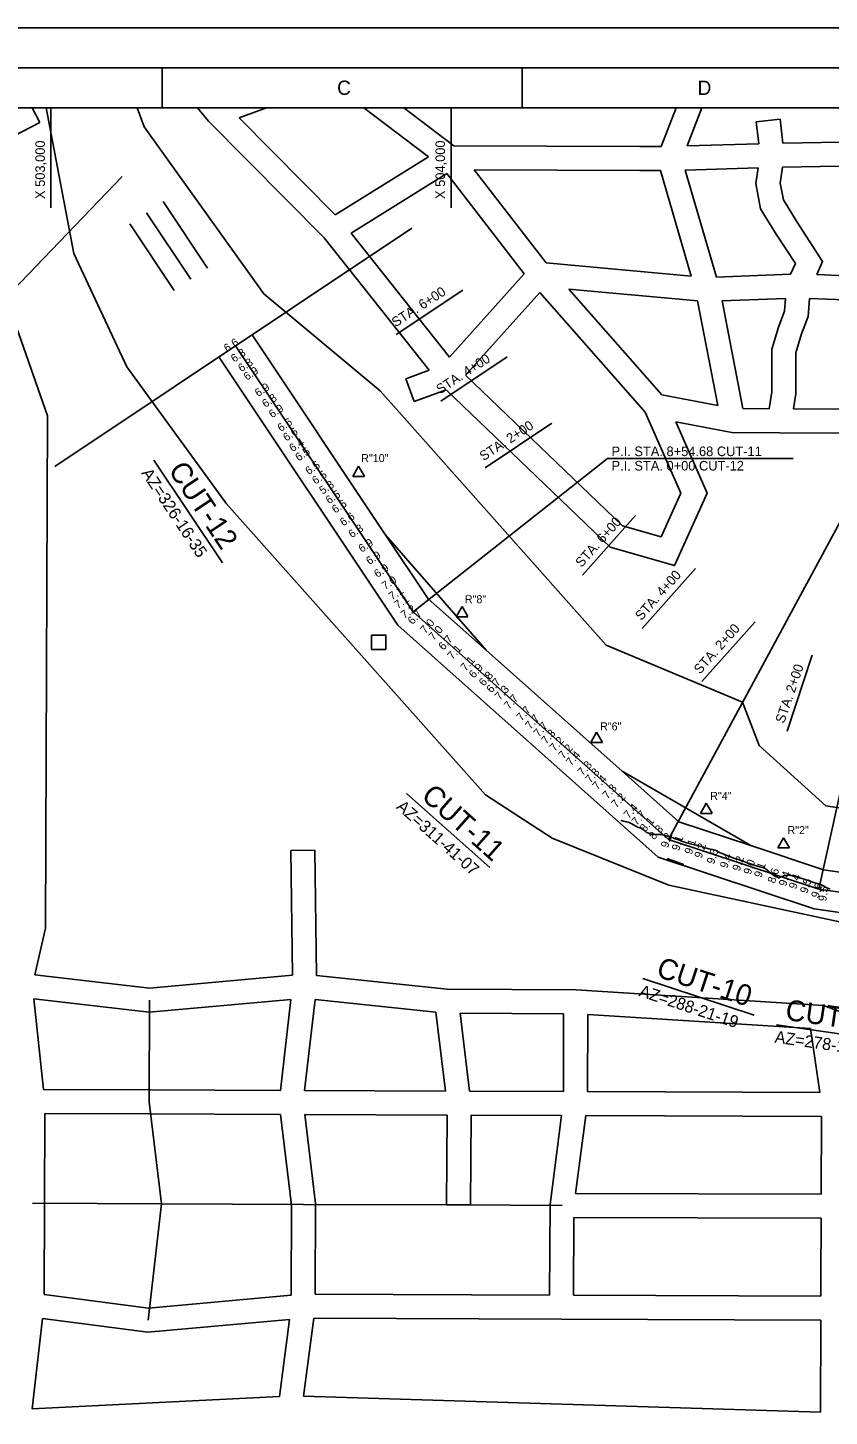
# Model space of a CAD drawing. Extents: x 501128 to 509328, y 1314906 to 1320706.
# Drawn here: x 502942 to 504945, y 1317236 to 1320706 of the extents above; entities that cross this region are included whole.
import ezdxf

# ---------------------------------------------------------------- set-up
doc = ezdxf.new("R2010")
doc.units = 0
for name, color, linetype in [('G-ANNO-TTLB', 7, 'Continuous'), ('Level 1', 7, 'Continuous'), ('Level 2', 7, 'Continuous'), ('Level 3', 7, 'Continuous'), ('Level 32', 7, 'Continuous'), ('Level 49', 7, 'Continuous'), ('Level 5', 7, 'Continuous'), ('Level 50', 7, 'Continuous'), ('Level 51', 7, 'Continuous'), ('Level 52', 7, 'Continuous'), ('Level 55', 7, 'Continuous'), ('Level 56', 7, 'Continuous'), ('Level 58', 7, 'Continuous'), ('Level 6', 7, 'Continuous')]:
    doc.layers.add(name, color=color, linetype=linetype)

msp = doc.modelspace()

# ---------------------------------------------------------------- linework, layer by layer
at = {"layer": 'G-ANNO-TTLB'}
for p, q in [((509228.1, 1320606.3), (501228.1, 1320606.3)), ((503278.1, 1320506.3), (503278.1, 1320606.3)), ((504178.1, 1320506.3), (504178.1, 1320606.3)), ((501478.1, 1320506.3), (509128.1, 1320506.3))]:
    msp.add_line(p, q, dxfattribs=at)
for points in [[(501128.1, 1314906.3), (509328.1, 1314906.3), (509328.1, 1320706.3), (501128.1, 1320706.3)], [(501128.1, 1314906.3), (509328.1, 1314906.3), (509328.1, 1320706.3), (501128.1, 1320706.3)], [(501128.1, 1320706.3), (509328.1, 1320706.3), (509328.1, 1314906.3), (501128.1, 1314906.3)]]:
    msp.add_lwpolyline(points, close=True, dxfattribs=at)
at = {"layer": 'Level 1'}
for points in [[(504577, 1318673.1), (504574.1, 1318674.2), (504568.6, 1318676.2), (504560.4, 1318679.3), (504554.8, 1318681.3), (504551.6, 1318682.4), (504551, 1318682.5), (504549.1, 1318683), (504545.9, 1318683.9), (504541.5, 1318685.3), (504537.1, 1318686.5), (504532.9, 1318687.8), (504528.7, 1318688.9), (504525.1, 1318689.7), (504522, 1318690), (504519.4, 1318689.9), (504514.9, 1318690), (504508.4, 1318690.4), (504500, 1318691.1), (504493.1, 1318692.8), (504487.8, 1318695.4), (504484, 1318699), (504480.1, 1318702.1), (504476, 1318704.5), (504471.7, 1318706.2), (504467, 1318708.4), (504461.9, 1318711.1), (504456.3, 1318714.1), (504451.9, 1318716.5), (504448.6, 1318718.2), (504446.4, 1318719.3), (504442.9, 1318720.6), (504438, 1318721.9), (504431.8, 1318723.4), (504427.7, 1318724.3), (504425.7, 1318724.5), (504426, 1318724), (504426.1, 1318723.7), (504426.1, 1318723.5), (504425.9, 1318723.3)], [(504733.7, 1318621.6), (504730.6, 1318622.9), (504730.2, 1318623.3), (504727, 1318624.4), (504721.1, 1318626.3), (504712.4, 1318629.1), (504706.1, 1318631.1), (504702.2, 1318632.3), (504700.7, 1318632.8), (504696.8, 1318634.4), (504690.4, 1318637), (504681.7, 1318640.7), (504675.3, 1318643.4), (504671.2, 1318645.1), (504669.5, 1318645.9), (504667.7, 1318646.8), (504665.8, 1318647.9), (504663.9, 1318649), (504659.7, 1318650.4), (504653.2, 1318652.1), (504644.5, 1318654.1), (504638.4, 1318655.6), (504634.8, 1318656.6), (504633.9, 1318657), (504630.7, 1318658), (504625.2, 1318659.5), (504617.5, 1318661.7), (504612.2, 1318663.1), (504609.3, 1318663.8), (504608.7, 1318663.8), (504605.1, 1318664.7), (504598.2, 1318666.6), (504588.2, 1318669.4), (504581.4, 1318671.3), (504577.9, 1318672.5), (504577.6, 1318672.7), (504577.4, 1318672.9), (504577.2, 1318673.1), (504577, 1318673.1)], [(504540.4, 1318630.1), (504542.2, 1318629.1), (504544, 1318628.3), (504546.9, 1318627.2), (504550.7, 1318625.9), (504554.3, 1318624.7), (504557.6, 1318623.5), (504560.6, 1318622.5), (504563.2, 1318621.6), (504565.4, 1318620.8), (504567.2, 1318620), (504569.3, 1318619.2), (504571.7, 1318618.4), (504574.4, 1318617.5), (504576.7, 1318616.7), (504578.6, 1318616), (504581.5, 1318614.9)], [(504947.6, 1318553.6), (504943.6, 1318554.6), (504941.6, 1318555.5), (504939.1, 1318556.8), (504935.9, 1318558.6), (504932.2, 1318560.8), (504928.8, 1318562.5), (504925.9, 1318563.8), (504923.4, 1318564.6), (504917.1, 1318566.8), (504906.9, 1318570.2), (504892.8, 1318574.9), (504882.7, 1318578.2), (504876.5, 1318580.1), (504874.3, 1318580.5), (504872.4, 1318581), (504870.7, 1318581.5), (504869.3, 1318581.9), (504866.2, 1318582.9), (504861.4, 1318584.2), (504854.8, 1318586.1), (504850.2, 1318587.4), (504847.7, 1318588.1), (504847.1, 1318588.3), (504845, 1318588.2), (504841.4, 1318588), (504836.2, 1318587.5), (504831.5, 1318586.5), (504827.2, 1318585), (504823.4, 1318582.9), (504820.3, 1318581.8), (504817.8, 1318581.8), (504816, 1318582.8), (504814.2, 1318583.7), (504812.4, 1318584.4), (504810.5, 1318584.8), (504807.2, 1318586.9), (504802.4, 1318590.7), (504796.1, 1318596.1), (504791.3, 1318600.1), (504788, 1318602.7), (504786.2, 1318603.9), (504784.8, 1318604.8), (504784, 1318605.2), (504783.7, 1318605.3), (504780.5, 1318606.3), (504774.6, 1318608), (504765.8, 1318610.5), (504757.1, 1318613.3), (504748.3, 1318616.3), (504739.6, 1318619.4), (504733.7, 1318621.6)]]:
    msp.add_lwpolyline(points, dxfattribs=at)
at = {"layer": 'Level 2'}
for p, q in [((503000, 1320256.3), (503000, 1320506.3)), ((504000, 1320256.3), (504000, 1320506.3))]:
    msp.add_line(p, q, dxfattribs=at)
at = {"layer": 'Level 32'}
for p, q in [((502953.1, 1320506.3), (502972, 1320469.9)), ((503393.9, 1320472.8), (503366.5, 1320506.3)), ((503538.5, 1320506.3), (503470.3, 1320481)), ((503943.9, 1320384.1), (503782.4, 1320506.3)), ((504006.9, 1320411.6), (503881.8, 1320506.3)), ((504525, 1320409.6), (504562.2, 1320506.3)), ((504589.8, 1320410.9), (504626.5, 1320506.3)), ((502770.6, 1320365.3), (502972, 1320469.9)), ((503683.1, 1320181), (503393.9, 1320472.8)), ((503710.1, 1320239.1), (503470.3, 1320481)), ((504762.8, 1320471.1), (504822.4, 1320478)), ((504769.1, 1320416.3), (504762.8, 1320471.1)), ((504829.3, 1320417.8), (504822.4, 1320478)), ((505021.6, 1320421.6), (504829.3, 1320417.8)), ((504472.1, 1320409.8), (504006.9, 1320411.6)), ((504525, 1320409.6), (504472.1, 1320409.8)), ((504769.1, 1320416.3), (504589.8, 1320410.9)), ((503943.9, 1320384.1), (503710.1, 1320239.1)), ((504237.4, 1320118.6), (504058, 1320351.4)), ((504471.9, 1320349.8), (504058, 1320351.4)), ((504767.5, 1320356.2), (504585.3, 1320350.7)), ((505016.9, 1320361.5), (504828.4, 1320357.8)), ((503989.6, 1320341.8), (503750, 1320193.2)), ((504182.7, 1320091.3), (503989.6, 1320341.8)), ((504523.1, 1320349.6), (504471.9, 1320349.8)), ((504600, 1320085.8), (504523.1, 1320349.6)), ((504663.4, 1320082.9), (504585.3, 1320350.7)), ((503945.5, 1319850.1), (503683.1, 1320181)), ((503996.1, 1319882.8), (503750, 1320193.2)), ((504600, 1320085.8), (504237.4, 1320118.6)), ((504182.7, 1320091.3), (503996.1, 1319882.8)), ((504848.7, 1320090.5), (504663.4, 1320082.9)), ((504986.3, 1320086.1), (504913.9, 1320089.3)), ((504221.5, 1320044.7), (504036.4, 1319837.9)), ((504485.3, 1319745.3), (504221.5, 1320044.7)), ((504616, 1320024.1), (504294, 1320053.3)), ((504526.7, 1319789.1), (504294, 1320053.3)), ((504666.6, 1319762.3), (504616, 1320024.1)), ((504835.9, 1320029.9), (504677.2, 1320023.4)), ((504729.3, 1319754.4), (504677.2, 1320023.4)), ((504983.8, 1320026.1), (504896.1, 1320030)), ((503945.5, 1319850.1), (503887.3, 1319828.4)), ((504428.2, 1319461.6), (504036.4, 1319837.9)), ((503908.2, 1319772.2), (503887.3, 1319828.4)), ((503987.5, 1319801.6), (503908.2, 1319772.2)), ((504397.4, 1319408), (503987.5, 1319801.6)), ((504666.6, 1319762.3), (504526.7, 1319789.1)), ((504794.9, 1319754.2), (504729.3, 1319754.4)), ((504991.3, 1319753.4), (504855.6, 1319753.9)), ((504701.6, 1319694.5), (504561.4, 1319721.4)), ((504820.6, 1319694.1), (504701.6, 1319694.5)), ((505022, 1319693.3), (504820.6, 1319694.1)), ((502986.3, 1318455.4), (502987.2, 1318676.8)), ((503599.2, 1318649.6), (503659.2, 1318650.4)), ((503603.4, 1318338.1), (503599.2, 1318649.6)), ((503663.4, 1318337.8), (503659.2, 1318650.4)), ((502960.1, 1318339.4), (502986.3, 1318455.4)), ((503246.6, 1318306.1), (502960.1, 1318339.4)), ((503603.4, 1318338.1), (503246.6, 1318306.1)), ((503990.3, 1318303), (503663.4, 1318337.8)), ((502981.6, 1318052.4), (502957.3, 1318279.4)), ((503245.8, 1318245.7), (502957.3, 1318279.4)), ((503599.7, 1318277.6), (503245.8, 1318245.7)), ((503573.6, 1318050.1), (503599.7, 1318277.6)), ((503633.9, 1318049.9), (503660.1, 1318277.8)), ((503961.8, 1318245.7), (503660.1, 1318277.8)), ((504312.5, 1318301.8), (503990.3, 1318303)), ((504931.1, 1318262.7), (504312.5, 1318301.8)), ((503986.1, 1318048.6), (503961.8, 1318245.7)), ((504046.5, 1318048.3), (504022.6, 1318242.9)), ((504281.4, 1318241.9), (504022.6, 1318242.9)), ((504280.6, 1318047.4), (504281.4, 1318241.9)), ((504340.6, 1318047.2), (504341.4, 1318239.8)), ((504898.5, 1318204.7), (504341.4, 1318239.8)), ((504996, 1318238.1), (504931.1, 1318262.7)), ((504921.5, 1318045), (504898.5, 1318204.7)), ((503245.3, 1318051.4), (502981.6, 1318052.4)), ((503573.6, 1318050.1), (503245.3, 1318051.4)), ((503986.1, 1318048.6), (503633.9, 1318049.9)), ((504280.6, 1318047.4), (504046.5, 1318048.3)), ((504921.5, 1318045), (504340.6, 1318047.2)), ((502983.7, 1317767.9), (502984.5, 1317992.4)), ((503245.1, 1317991.4), (502984.5, 1317992.4)), ((503573.8, 1317990.1), (503245.1, 1317991.4)), ((503601.6, 1317763.7), (503573.8, 1317990.1)), ((503989.9, 1317988.5), (503634.2, 1317989.9)), ((503661.6, 1317767.2), (503634.2, 1317989.9)), ((503989, 1317764.1), (503989.9, 1317988.5)), ((504049, 1317763.8), (504049.9, 1317988.3)), ((504276.4, 1317987.4), (504049.9, 1317988.3)), ((504247.3, 1317765), (504276.4, 1317987.4)), ((504311.4, 1317792.8), (504336.8, 1317987.2)), ((504926.1, 1317984.9), (504336.8, 1317987.2)), ((504925.3, 1317790.5), (504926.1, 1317984.9)), ((504925.3, 1317790.5), (504311.4, 1317792.8)), ((502982.8, 1317539.9), (502983.7, 1317767.9)), ((503600.7, 1317538.4), (503601.6, 1317763.7)), ((503660.7, 1317540.8), (503661.6, 1317767.2)), ((503989, 1317764.1), (504049, 1317763.8)), ((504246.4, 1317538.6), (504247.3, 1317765)), ((504306.4, 1317538.3), (504307.2, 1317732.8)), ((504925.1, 1317730.5), (504307.2, 1317732.8)), ((504924.5, 1317578.7), (504925.1, 1317730.5)), ((504924.3, 1317536), (504924.5, 1317578.7)), ((504246.4, 1317538.6), (503660.7, 1317540.8)), ((503243.7, 1317506.3), (502982.8, 1317539.9)), ((503600.7, 1317538.4), (503243.7, 1317506.3)), ((504924.3, 1317536), (504306.4, 1317538.3)), ((502953.1, 1317254.6), (502979, 1317479.9)), ((503242.5, 1317445.9), (502979, 1317479.9)), ((503596, 1317477.7), (503242.5, 1317445.9)), ((503570.9, 1317285.3), (503596, 1317477.7)), ((503631.4, 1317285.6), (503656.9, 1317480.8)), ((504276.2, 1317478.5), (503656.9, 1317480.8)), ((504924.1, 1317476), (504276.2, 1317478.5)), ((504923.2, 1317246), (504924.1, 1317476)), ((503570.9, 1317285.3), (502953.1, 1317254.6)), ((504923.2, 1317246), (503631.4, 1317285.6))]:
    msp.add_line(p, q, dxfattribs=at)
for points in [[(502987.2, 1318676.8), (502991.3, 1319736.3), (502770.6, 1320365.3)], [(504848.7, 1320090.5), (504860.5, 1320116.7), (504812.7, 1320190.8), (504773.7, 1320254), (504761.5, 1320316.9), (504767.5, 1320356.2)], [(504913.9, 1320089.3), (504928.6, 1320121.9), (504863.4, 1320222.8), (504830.5, 1320276.2), (504822.4, 1320318.1), (504828.4, 1320357.8)], [(504794.9, 1319754.2), (504801.3, 1319796.1), (504801.7, 1319903), (504819, 1319960.5), (504833.5, 1319998.2), (504835.9, 1320029.9)], [(504855.6, 1319753.9), (504861.3, 1319791.5), (504861.7, 1319894.1), (504875.8, 1319941.1), (504892.6, 1319984.8), (504896.1, 1320030)], [(504428.2, 1319461.6), (504525.1, 1319433.9), (504574.1, 1319543.2), (504485.3, 1319745.3)], [(504397.4, 1319408), (504558.6, 1319361.9), (504639.8, 1319543), (504561.4, 1319721.4)]]:
    msp.add_lwpolyline(points, dxfattribs=at)
at = {"layer": 'Level 5'}
for points in [[(502988.5, 1320506.3), (503056.9, 1320142.4), (503189.4, 1319858.7), (503438.4, 1319516.2), (504086.3, 1318789.2), (504252.7, 1318680.4), (504544, 1318562.8), (505451.9, 1318368.4), (505926.4, 1318183.7), (506109.2, 1317999.8), (506132.4, 1317399.6), (506064.1, 1316858.1), (505929.2, 1316350.1), (505744.2, 1315800.6), (505760.3, 1315617.2), (505843.1, 1315416.9), (505867.7, 1315106.3)], [(506133.9, 1315106.3), (506134.1, 1315191), (506100.8, 1315216.1), (506088.6, 1315786), (506137, 1316149.5), (506179.5, 1316449.4), (506272.3, 1316790.8), (506340.8, 1317415.6), (506508.7, 1317823.5), (506567.6, 1317998.4), (506518.7, 1318373.6), (506369, 1318507.4), (506052.8, 1318658.3), (505377.9, 1318693.7), (504936.3, 1318761.6), (504770.1, 1318912.2), (504728.7, 1319020.6), (504387.5, 1319163.3), (503822.6, 1319798.4), (503531.7, 1320041), (503232.9, 1320458.6), (503215.7, 1320506.3)]]:
    msp.add_lwpolyline(points, dxfattribs=at)
at = {"layer": 'Level 50'}
for p, q in [((503835.7, 1319440.1), (503502.6, 1319939.2)), ((503867.1, 1319212.9), (503419.4, 1319883.6)), ((504087.8, 1319150.4), (503835.7, 1319440.1)), ((503835.7, 1319440.1), (503943.2, 1319279.1)), ((503943.2, 1319279.1), (504087.8, 1319150.4)), ((504517.9, 1318633.4), (503867.1, 1319212.9)), ((504427.4, 1318848), (504087.8, 1319150.4)), ((504749, 1318662.1), (504427.4, 1318848)), ((504427.4, 1318848), (504569, 1318721.8)), ((504569, 1318721.8), (504749, 1318662.1)), ((504930.9, 1318601.8), (504749, 1318662.1)), ((504907.8, 1318504.1), (504517.9, 1318633.4)), ((505117.2, 1318575), (504930.9, 1318601.8)), ((505102.9, 1318476.1), (504907.8, 1318504.1))]:
    msp.add_line(p, q, dxfattribs=at)
at = {"layer": 'Level 51'}
for p, q in [((503428.8, 1319368.5), (503257.2, 1319625.6)), ((504096.5, 1318607), (503888.8, 1318792)), ((504757.3, 1318237.9), (504479.4, 1318330.1)), ((505110.8, 1318171.8), (504813.4, 1318214.5))]:
    msp.add_line(p, q, dxfattribs=at)
at = {"layer": 'Level 52'}
for p, q in [((503754.3, 1319585.1), (503769, 1319610.6)), ((503769, 1319610.6), (503783.6, 1319585.3)), ((503783.7, 1319585.1), (503754.3, 1319585.1)), ((504012.9, 1319234.2), (504027.5, 1319259.6)), ((504027.5, 1319259.6), (504042.1, 1319234.4)), ((504042.2, 1319234.2), (504012.9, 1319234.2)), ((504349, 1318919.9), (504363.7, 1318945.4)), ((504363.7, 1318945.4), (504378.3, 1318920.1)), ((504378.4, 1318919.9), (504349, 1318919.9)), ((504623.1, 1318742.7), (504637.8, 1318768.1)), ((504637.8, 1318768.1), (504652.4, 1318742.8)), ((504652.5, 1318742.7), (504623.1, 1318742.7)), ((504816.3, 1318656.2), (504831, 1318681.6)), ((504845.7, 1318656.2), (504816.3, 1318656.2)), ((504831, 1318681.6), (504845.6, 1318656.3))]:
    msp.add_line(p, q, dxfattribs=at)
msp.add_lwpolyline([(503801.2, 1319188.4), (503837.2, 1319188.4), (503837.2, 1319152.4), (503801.2, 1319152.4)], close=True, dxfattribs=at)
at = {"layer": 'Level 55'}
for p, q in [((503245.2, 1318021.4), (503246.2, 1318275.9)), ((503276.5, 1317766.8), (503245.2, 1318021.4)), ((503276.5, 1317766.8), (502953.7, 1317768.1)), ((503243.1, 1317476.1), (503276.5, 1317766.8)), ((503631.6, 1317765.4), (503276.5, 1317766.8)), ((504019, 1317763.9), (503631.6, 1317765.4)), ((504277.3, 1317762.9), (504019, 1317763.9))]:
    msp.add_line(p, q, dxfattribs=at)
at = {"layer": 'Level 56'}
for p, q in [((503178.4, 1320334.8), (502752.4, 1319891.8)), ((503391.6, 1320105.5), (503280.5, 1320271.9)), ((503308.4, 1320050), (503197.4, 1320216.3)), ((503350, 1320077.8), (503239, 1320244.1)), ((503863.2, 1319939.4), (504029.5, 1320050.4)), ((503974.2, 1319773), (504140.6, 1319884.1)), ((504085.2, 1319606.7), (504251.6, 1319717.7)), ((503905.2, 1319246), (504391.1, 1319629.6)), ((504391.1, 1319629.6), (504855, 1319629.6)), ((504543.5, 1318677.6), (505040.5, 1319598.4)), ((504328.1, 1319338), (504461.1, 1319487.4)), ((504919.4, 1318552.9), (505112.2, 1319433.1)), ((504477.5, 1319205), (504610.5, 1319354.4)), ((504626.9, 1319072), (504759.9, 1319221.4)), ((504839.8, 1318948.1), (504902.7, 1319137.9))]:
    msp.add_line(p, q, dxfattribs=at)
at = {"layer": 'Level 58'}
msp.add_line((503009.5, 1319610), (503901.9, 1320205.7), dxfattribs=at)
at = {"layer": 'Level 6'}
for p, q in [((503905.2, 1319246), (503461, 1319911.4)), ((504543.5, 1318677.6), (503905.2, 1319246)), ((504919.4, 1318552.9), (504543.5, 1318677.6)), ((505110.1, 1318525.5), (504919.4, 1318552.9))]:
    msp.add_line(p, q, dxfattribs=at)

# ---------------------------------------------------------------- texts
at = {"layer": 'G-ANNO-TTLB'}
for s, p in [('C', (503715.3, 1320538.5)), ('D', (504616.1, 1320538.5))]:
    msp.add_text(s, height=35.7, dxfattribs=at).set_placement(p)
at = {"layer": 'Level 3'}
for s, p in [('X 503,000', (502985, 1320278.3)), ('X 504,000', (503985, 1320278.3))]:
    msp.add_text(s, height=24, rotation=90, dxfattribs=at).set_placement(p)
at = {"layer": 'Level 49'}
for s, rotation, p in [('6.6', 33.7236, (503440.4, 1319894.7)), ('6.8', 33.7236, (503457.9, 1319869)), ('6.8', 33.7236, (503475.9, 1319845)), ('6.9', 33.7236, (503489.8, 1319823.9)), ('6.9', 33.7236, (503517.8, 1319782.9)), ('6.8', 33.7236, (503535.9, 1319756)), ('6.9', 33.7236, (503552.8, 1319729.9)), ('6.6', 33.7236, (503574.4, 1319695.7)), ('6.6', 33.7236, (503588.4, 1319671.7)), ('6.4', 33.7236, (503603.9, 1319645)), ('6.5', 33.7236, (503618.9, 1319622)), ('6.5', 33.7236, (503643.9, 1319588)), ('6.5', 33.7236, (503660.9, 1319564)), ('5.8', 33.7236, (503678.9, 1319539)), ('6.5', 33.7236, (503694.9, 1319515)), ('6.6', 33.7236, (503710.4, 1319491.7)), ('6.6', 33.7236, (503730.4, 1319459.7)), ('6.8', 33.7236, (503751.9, 1319430)), ('6.9', 33.7236, (503776.8, 1319393.9)), ('6.9', 33.7236, (503795.8, 1319362.9)), ('6.9', 33.7236, (503815.8, 1319330.9)), ('7.0', 33.7236, (503835.2, 1319300.5)), ('7.1', 33.7236, (503852.5, 1319274.4)), ('7.1', 33.7236, (503866.5, 1319253.4)), ('7.2', 33.7236, (503882.9, 1319228)), ('6.7', 48.3147, (503904.1, 1319213.1)), ('7.0', 48.3147, (503935.6, 1319190.4)), ('7.0', 48.3147, (503956.6, 1319173.4)), ('6.7', 48.3147, (503981.1, 1319149.1)), ('7.1', 48.3147, (504003.6, 1319125.6)), ('7.1', 48.3147, (504036.6, 1319096.6)), ('6.9', 48.3147, (504057.1, 1319079)), ('6.8', 48.3147, (504082.1, 1319059.1)), ('6.7', 48.3147, (504101.1, 1319042.1)), ('7.3', 48.3147, (504122.1, 1319024.1)), ('7.7', 48.3147, (504145.1, 1319001.1)), ('7.7', 48.3147, (504176.1, 1318972.1)), ('7.7', 48.3147, (504198.1, 1318951.1)), ('7.7', 48.3147, (504219.1, 1318932.1)), ('7.3', 48.3147, (504238.1, 1318914.1)), ('7.2', 48.3147, (504259.1, 1318896.1)), ('7.2', 48.3147, (504281.1, 1318877.1)), ('7.4', 48.3147, (504300.1, 1318860.1)), ('7.8', 48.3147, (504329.1, 1318835.1)), ('7.8', 48.3147, (504348.1, 1318817.1)), ('7.4', 48.3147, (504366.1, 1318800.1)), ('7.3', 48.3147, (504391.1, 1318777.1)), ('7.2', 48.3147, (504413.1, 1318755.1)), ('7.4', 48.3147, (504444.1, 1318728.1)), ('7.7', 48.3147, (504464.1, 1318711.1)), ('8.1', 48.3147, (504484.6, 1318694.6)), ('8.8', 48.3147, (504507.1, 1318675.1)), ('9.2', 71.6447, (504542, 1318654.9)), ('9.1', 71.6447, (504569.3, 1318647.6)), ('9.1', 71.6447, (504601.3, 1318638.6)), ('9.2', 71.6447, (504626, 1318628.9)), ('9.6', 71.6447, (504656.9, 1318614.4)), ('9.4', 71.6447, (504690, 1318603.9)), ('9.2', 71.6447, (504721, 1318596.9)), ('9.0', 71.6447, (504748.8, 1318588.1)), ('9.1', 71.6447, (504775.3, 1318580.6)), ('8.6', 71.6447, (504808.9, 1318566.4)), ('9.4', 71.6447, (504837, 1318558.9)), ('9.4', 71.6447, (504862, 1318551.9)), ('9.5', 71.6447, (504890, 1318540.9)), ('9.6', 71.6447, (504917.9, 1318529.4)), ('9.5', 81.8319, (504937.4, 1318521.9))]:
    msp.add_text(s, height=20, rotation=rotation, dxfattribs=at).set_placement(p)
at = {"layer": 'Level 51'}
for s, height, rotation, p in [('AZ=326-16-35', 30, 303.7235, (503224.7, 1319593.2)), ('CUT-12', 52, 303.7235, (503292, 1319600.4)), ('CUT-11', 52, 318.3149, (503922.7, 1318781.8)), ('AZ=311-41-07', 30, 318.3149, (503861.2, 1318756.3)), ('CUT-10', 52, 341.6447, (504510.2, 1318335.7)), ('AZ=288-21-19', 30, 341.6447, (504467.6, 1318286.6)), ('CUT-9B', 52, 351.832, (504833.4, 1318226.8)), ('AZ=278-10-05', 30, 351.832, (504807.6, 1318169.9))]:
    msp.add_text(s, height=height, rotation=rotation, dxfattribs=at).set_placement(p)
at = {"layer": 'Level 52'}
for s, p in [('R"10"', (503775.5, 1319620.7)), ('R"8"', (504034.5, 1319267.9)), ('R"6"', (504372.4, 1318950.2)), ('R"4"', (504647.7, 1318776.2)), ('R"2"', (504840.9, 1318690.8))]:
    msp.add_text(s, height=20, dxfattribs=at).set_placement(p)
at = {"layer": 'Level 56'}
for s, rotation, p in [('STA. 6+00', 33.1566, (503861.5, 1319957.3)), ('STA. 4+00', 33.1566, (503972.6, 1319789.8)), ('STA. 2+00', 33.1566, (504081, 1319622.7)), ('STA. 6+00', 48.4209, (504326.1, 1319356.1)), ('STA. 4+00', 48.4209, (504475.5, 1319223.1)), ('STA. 2+00', 48.4209, (504622.2, 1319089.3)), ('STA. 2+00', 71.1231, (504832.3, 1318966.3))]:
    msp.add_text(s, height=24, rotation=rotation, dxfattribs=at).set_placement(p)
for s, p in [('P.I. STA. 8+54.68 CUT-11', (504401.1, 1319635.6)), ('P.I. STA. 0+00 CUT-12', (504401.1, 1319599.6))]:
    msp.add_text(s, height=24, dxfattribs=at).set_placement(p)

doc.saveas('drawing.dxf')
